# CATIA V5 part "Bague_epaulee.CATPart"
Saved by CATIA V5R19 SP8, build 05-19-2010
Part number: Bague èpaulée
Revision: ANY
Definition: UNKNOWN
Nomenclature: Bague èpaulée
Source: Unknown
Bounding box of the stored display mesh (mm): x -5 to 5, y -4.99 to 4.99, z 0 to 5
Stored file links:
  D:\Documents\1_Travail\1 - ac-limoges.fr\OneDrive - ac-limoges.fr\STI2D_Turgot\2 -2I2D\3_SEQUENCE_Serre_Connectée\3- Spécificités\ITEC\EC 3 Ouverture automatique\Simulation  Ouverture Automatique\Bague_epaulee.CATPart
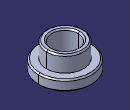
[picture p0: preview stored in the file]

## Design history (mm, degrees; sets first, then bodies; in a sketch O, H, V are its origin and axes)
Body1 "NONE" (main body)
  Solid1: solid without history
